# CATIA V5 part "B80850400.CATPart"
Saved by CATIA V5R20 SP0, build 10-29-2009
Part number: B80850400
Revision: 2
Definition: design
Nomenclature: B80850400
Source: made
Description: NOT SPECIFIED
Bounding box of the stored display mesh (mm): x -27.5 to 27.5, y -27.5 to 27.5, z 0 to 400
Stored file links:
  C:\Users\Raffaele\Desktop\3D X SITO CF\BOLEX\4-PILLAR REF 808\B80850400.CATPart
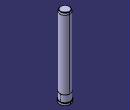
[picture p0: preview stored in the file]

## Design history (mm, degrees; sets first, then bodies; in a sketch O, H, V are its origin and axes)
Body1 "MANIFOLD_SOLID_BREP #450" (main body)
  Solid1: solid without history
